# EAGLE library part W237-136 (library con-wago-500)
WAGO SCREW CLAMP
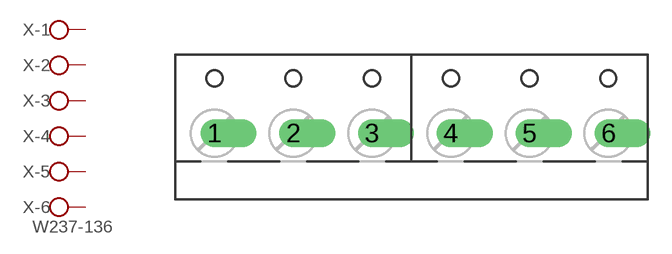
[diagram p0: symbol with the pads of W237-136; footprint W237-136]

Designator prefix X; gates -1=KL -2=KL -3=KL -4=KL -5=KL -6=KL+V

## W237-136  [W237-136]
1  -1:KL  pas
2  -2:KL  pas
3  -3:KL  pas
4  -4:KL  pas
5  -5:KL  pas
6  -6:KL  pas

## Footprint W237-136 (pad centres in mm)
WAGO SCREW CLAMP
drill 1.194 offset: 1 -12.5,-1.27; 2 -7.5,-1.27; 3 -2.5,-1.27; 4 2.5,-1.27; 5 7.5,-1.27; 6 12.5,-1.27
